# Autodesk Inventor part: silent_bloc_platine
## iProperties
Shininess: 64.0
Length Units: 11269
Angle Units: 11279
Time Units: 11290
Mass Units: 11283
Length Display Precision: 3
Angle Display Precision: 2
Compacted: True
Part Number: silent_bloc_platine
Document SubType Name: Modeling
Created: 2004-05
Material: Par défaut
Designer: David
Density: 0.0
Volumn: 0.0
Area: 0.0
PropertySet Name: Model Information
Control State: 0
Master: False
Checked Out: False
Author: David
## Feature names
1. Extrusion1
2. Extrusion2
3. Extrusion3
